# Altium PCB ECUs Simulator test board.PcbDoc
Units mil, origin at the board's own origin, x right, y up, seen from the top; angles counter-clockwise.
Board outline 2945 x 3010 mil, 2 copper layers (Top Layer, Bottom Layer), stack 12.8 mil thick; 62 components, 38 nets, 262 pads, 144 vias.
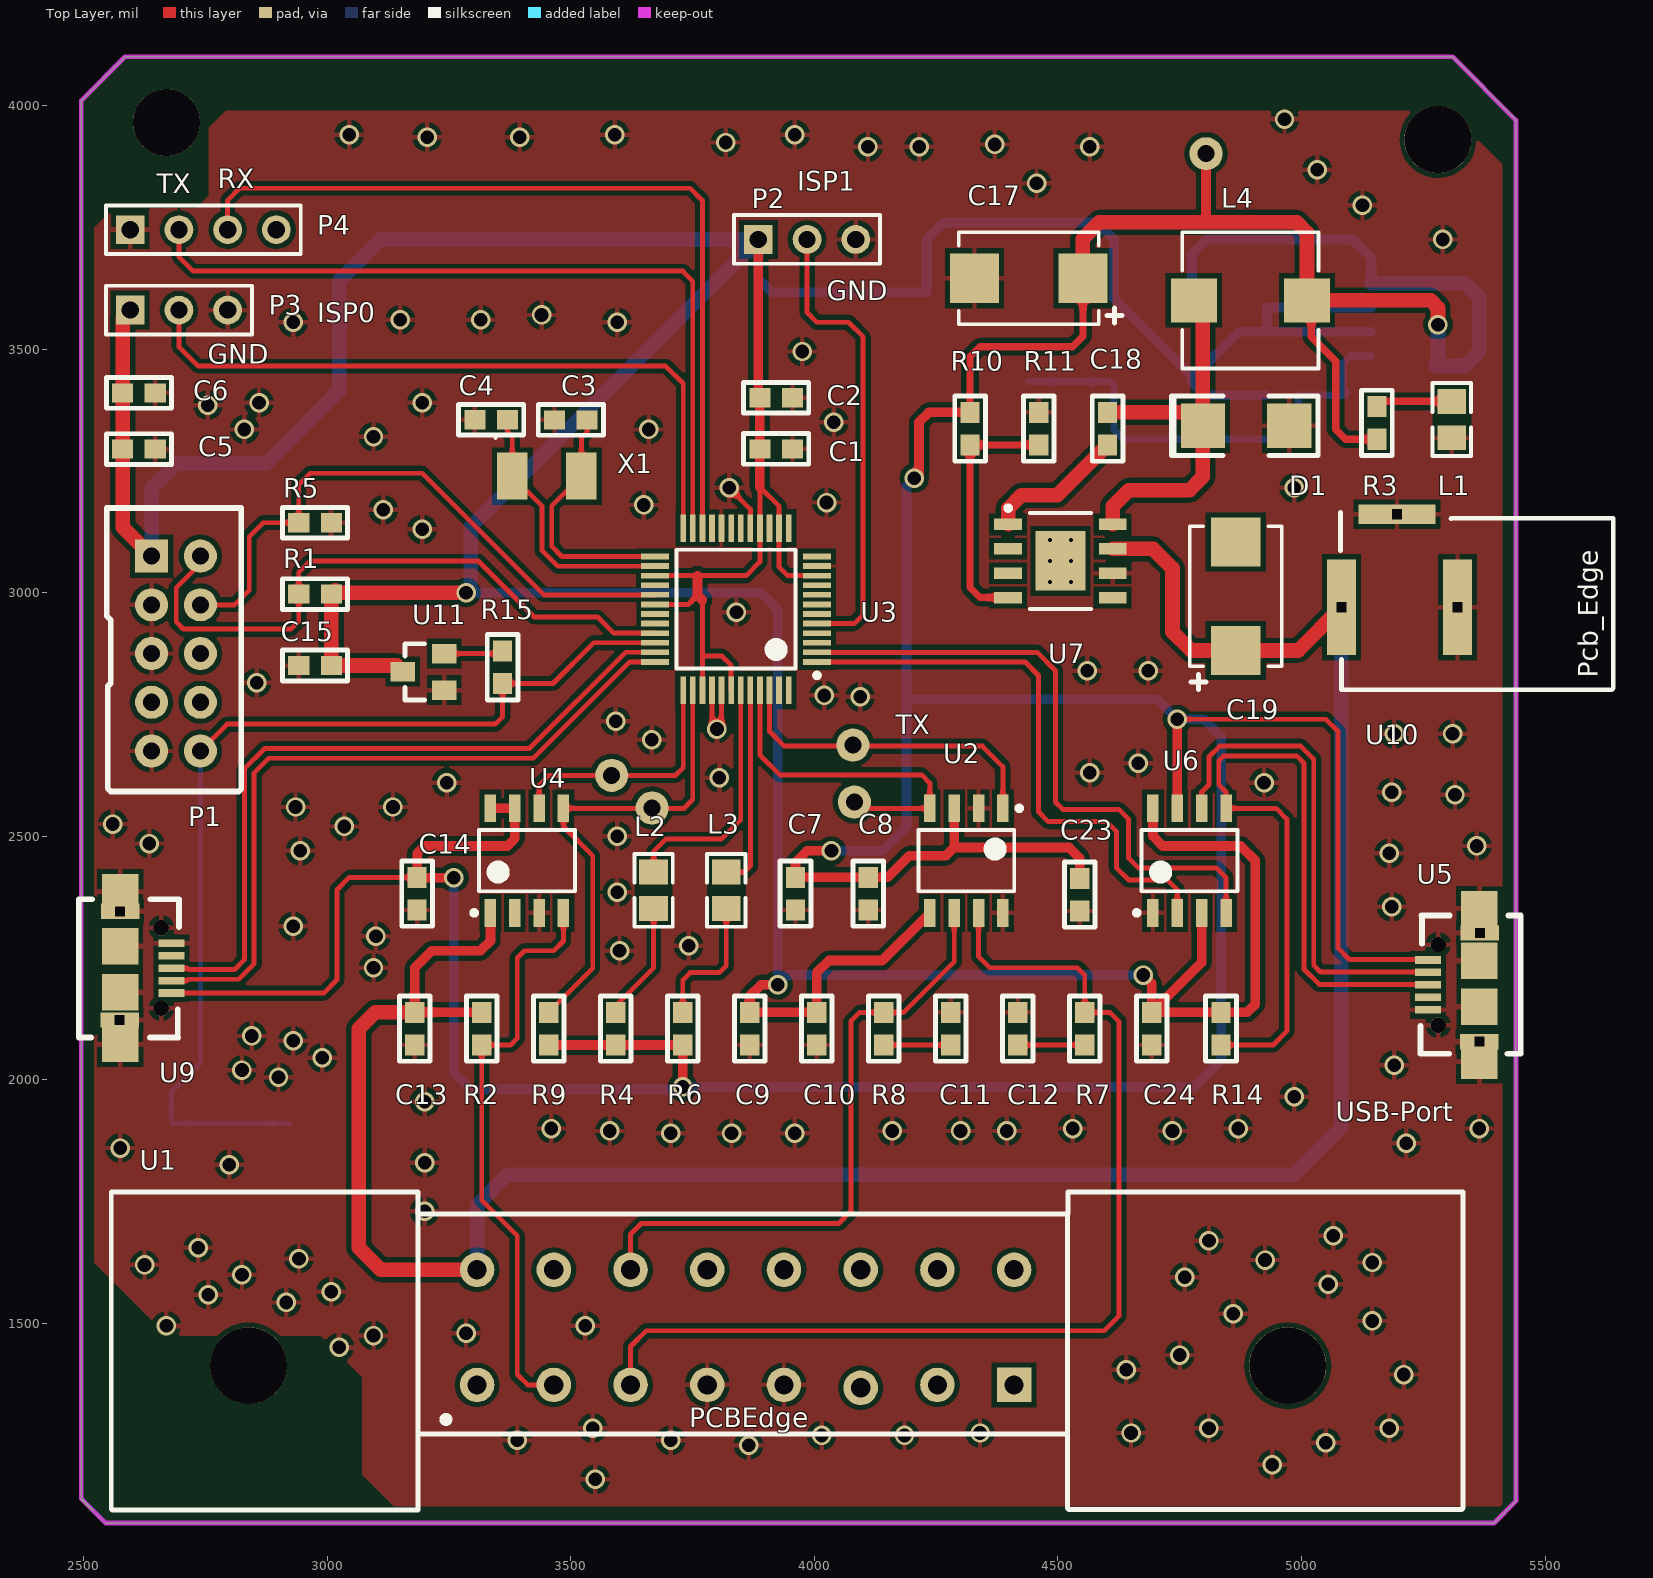
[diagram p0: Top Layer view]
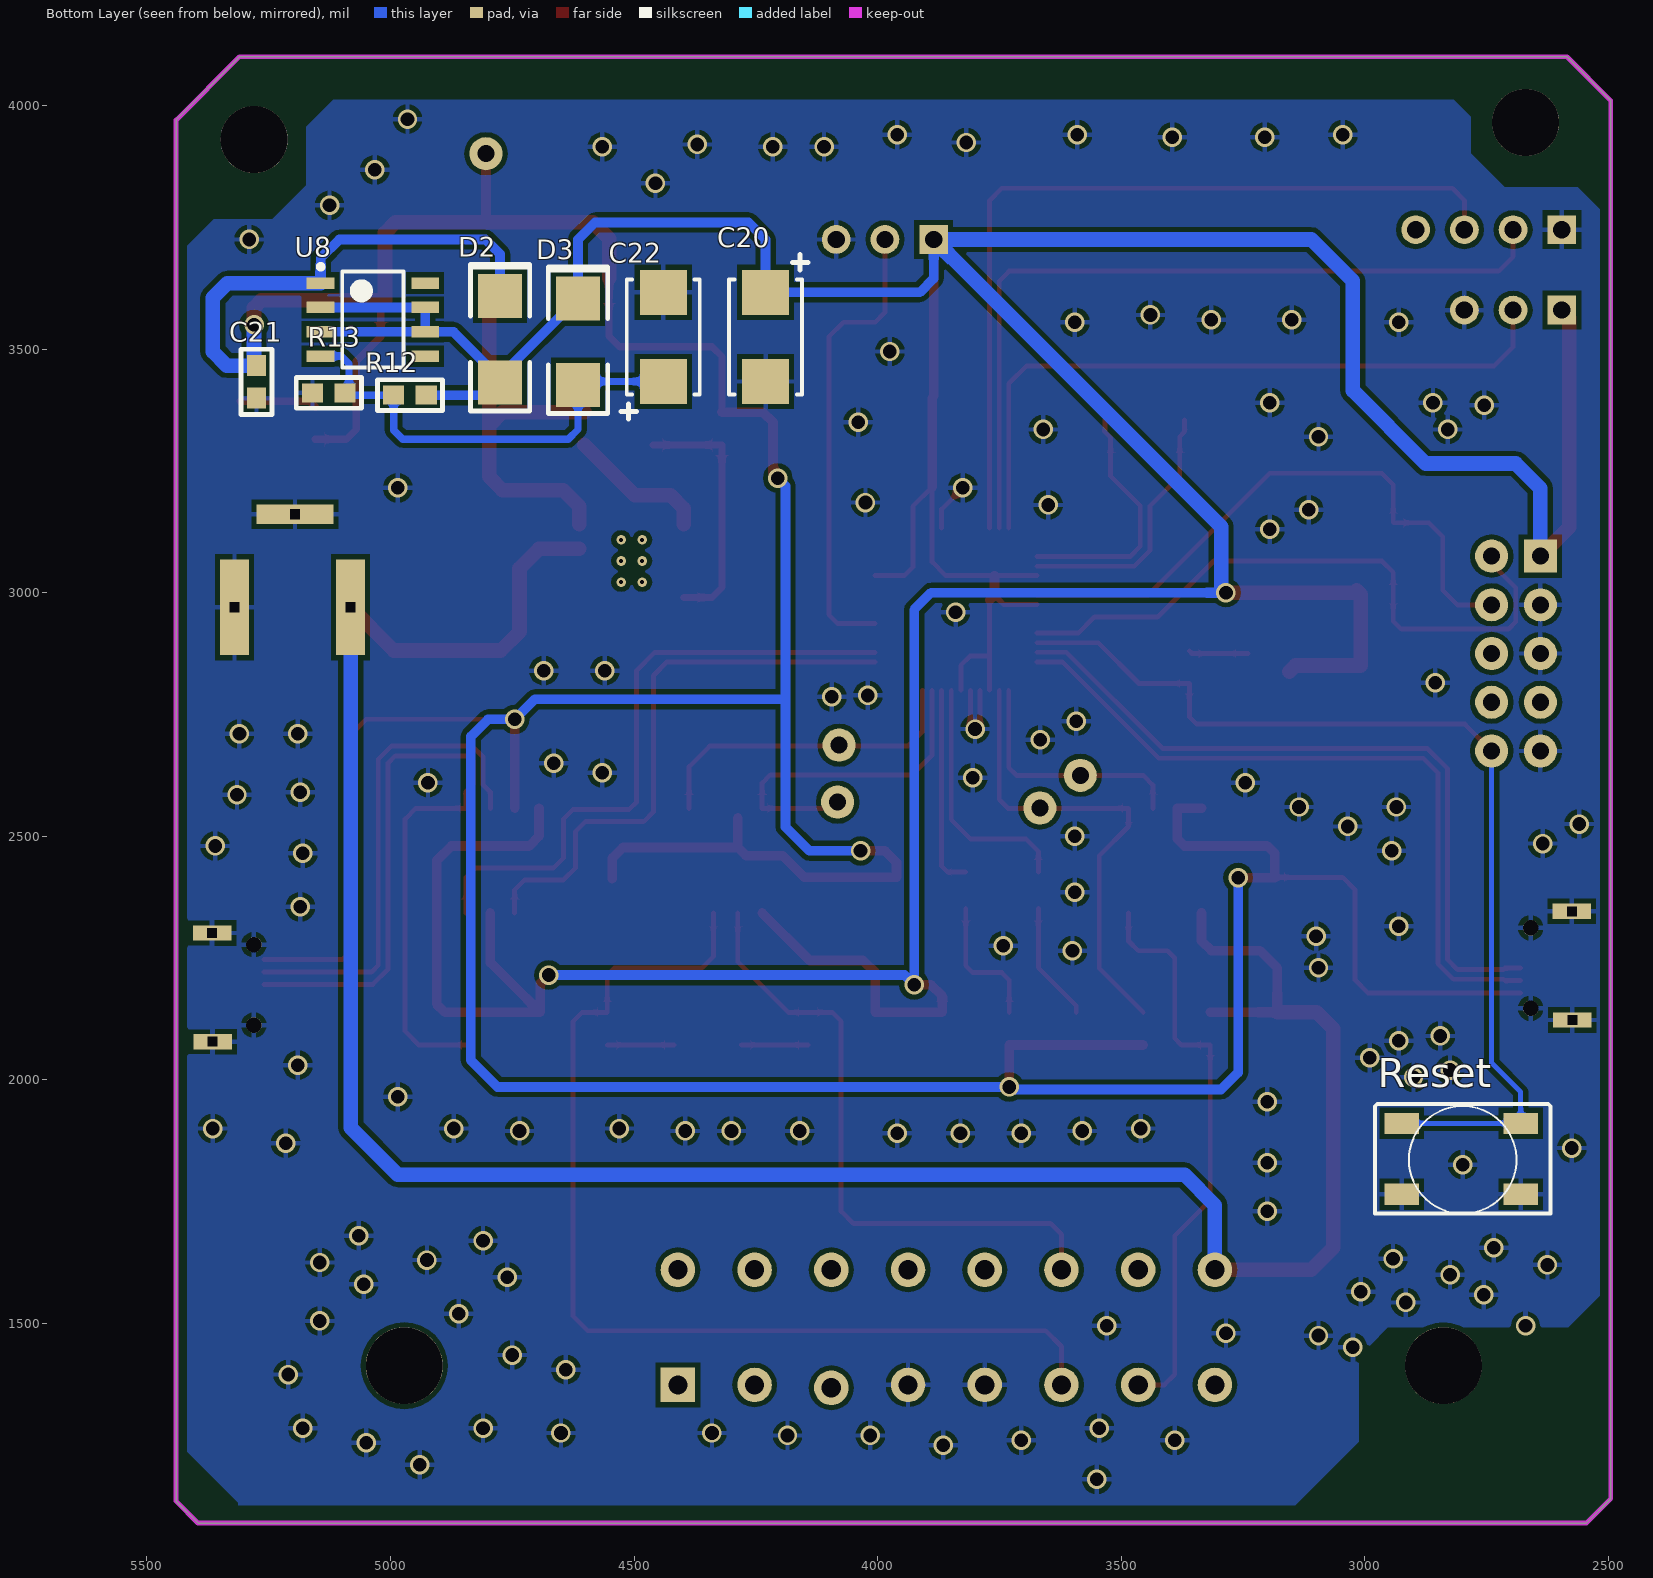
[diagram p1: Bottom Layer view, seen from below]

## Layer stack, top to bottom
Top Solder: solder mask 0.4, Solder Resist, Dk 3.5
Top Layer: signal copper 1.4
Dielectric 1: core 10, FR-4, Dk 4.2
Bottom Layer: signal copper 1.4
Bottom Solder: solder mask 0.4, Solder Resist, Dk 3.5

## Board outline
2495,1140 2495,4010 2585,4100 5310,4100 5440,3970 5440,1135 5395,1090 2545,1090

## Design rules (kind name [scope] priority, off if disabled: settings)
Clearance [All] p1: gap=10
DiffPairsRouting [All] p1: maxlimit=10 minlimit=10 mostfreqgap=10 toplayer_minwidth=10 toplayer_maxwidth=15 toplayer_prefwidth=15 bottomlayer_minwidth=10 bottomlayer_maxwidth=15 bottomlayer_prefwidth=15 maxuncoupledlength=500
PolygonConnect [All] p1: connectstyle=Relief reliefconductorwidth=10 reliefentries=4 polygonreliefangle="90 Angle" airgapwidth=10
RoutingVias [All] p1: holewidth=20 width=32 viastyle="Through Hole" minholewidth=15 minwidth=25 maxholewidth=28 maxwidth=40
SolderMaskExpansion [All] p1: expansion=4
Width [All] p1: maxlimit=30 minlimit=10 preferedwidth=10
29 further rules are at their usual default settings.

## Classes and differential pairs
component class USB: U9
component class Power: C17 C18 C19 C20 C21 C22 D1 D2 D3 L4 R10 R11 R12 R13 U7 U8 U10
component class PL2303A: C23 C24 R14 U5 U6
component class Core: C1 C2 C3 C4 C5 C6 C7 C8 C9 C10 C11 C12 C13 C14 C15 L1 L2 L3 P1 P2 P3 P4 R1 R2 R3 R4 R5 R6 R7 R8 R9 R15 Reset U1 U2 U3 U4 U11 X1

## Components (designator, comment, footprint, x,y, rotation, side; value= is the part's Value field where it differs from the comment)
C1 "10uF" 0603 3921.54,3295.39 r180 top
C2 "0.1uF" 0603 3921.54,3400.39 r180 top
C3 "22pF" 0603 3500,3355 r180 top
C4 "22pF" 0603 3336.54,3355.39 r180 top
C5 "4.7uF" 0603 2613.57,3295 r180 top
C6 "0.1uF" 0603 2613.57,3410.39 r180 top
C7 "0.1uF" 0603 3960.91,2382.1 r270 top
C8 "10uF" 0603 4110,2382.1 r270 top
C9 "10uF" 0603 3866.88,2105 r270 top
C10 "0.1uF" 0603 4004.41,2105 r270 top
C11 "560pF" 0603 4279.47,2105 r270 top
C12 "560pF" 0603 4417.01,2105 r270 top
C13 "0.1uF" 0603 3179.21,2105 r270 top
C14 "0.1uF" 0603 3185,2382.1 r90 top
C15 "0.1uF" 0603 2975,2850 r0 top
C17 "220uF" CAPM-7.0*4.5 4440,3645.32 r180 top
C18 "0.01uF" 0603 4602.18,3336.61 r90 top
C19 "10uF/16V" CAPM-7.0*4.5 4865,2992.46 r90 top
C20 "10uF/16V" CAPM-5.5*3.3 4230,3525 r270 bottom
C21 "0.1uF" 0603 5274.61,3432.62 r90 bottom
C22 "10uF/16V" CAPM-5.5*3.3 4440,3525 r90 bottom
C23 "10uF" 0603 4545,2380 r90 top
C24 "0.1uF" 0603 4692.86,2105 r90 top
D1 "B340A" DO214-AC 4886.16,3342.52 r180 top
D2 "1N4007" DO214-AC 4775,3520.2 r90 bottom
D3 "1N4007" DO214-AC 4615,3515 r90 bottom
L1 "LED" 0805 5308.41,3355.3 r270 top
L2 "LED" 0805 3670,2388.98 r90 top
L3 "LED" 0805 3819.09,2388.98 r90 top
L4 "4.7uH" 7*7*4-15uH 4895,3600.05 r0 top
P1 "Debug" JATG_10pin 2639.54,3075 r0 top
P2 "" HDR1X3 3885,3725 r0 top
P3 "" HDR1X3 2595.57,3580 r0 top
P4 "downloader" HDR1X4 2595.57,3745 r0 top
R1 "10K" 0603 2975,2997.3 r180 top
R2 "510R" 0603 3317.53,2105 r90 top
R3 "330R" 0603 5155,3348.43 r90 top
R4 "330R" 0603 3592.6,2105 r90 top
R5 "10K" 0603 2975,3143.8 r180 top
R6 "330R" 0603 3730.13,2105 r90 top
R7 "100R" 0603 4555.33,2105 r90 top
R8 "100R" 0603 4142.73,2105 r90 top
R9 "3.3K" 0603 3454.28,2105 r270 top
R10 "10K" 0603 4320,3336.61 r90 top
R11 "3.24K" 0603 4460.3,3336.61 r270 top
R12 "470R" 0603 4960,3405 r180 bottom
R13 "820R" 0603 5126.54,3409.61 r180 bottom
R14 "1.5K" 0603 4835,2105 r90 top
R15 "100K" 0603 3360.39,2846.93 r90 top
Reset "Button" BUtton-T4 2924.09,1910.67 r180 bottom (schematic designator S1)
U1 "OBD-Connector" OBD-Female 3307.64,1373.78 r0 top
U2 "TJF1051T / 3" TJF1051 4305,2448 r270 top
U3 "LPC1549" LPC1549JBD48 3840,2970 r180 top
U4 "MC33660EFR2" SOP-8 3410,2450 r90 top
U5 "MicroUSB" Micro-USB 5365,2037.4 r180 top
U6 "PL2303SA" SOP-8 4770,2450 r90 top
U7 "TPS5430" TPS5430 4505,3065 r0 top
U8 "LM317L" LM317L 5035,3560.44 r180 bottom
U9 "MicroUSB" Micro-USB 2575,2386.69 r0 top
U10 "DC-12V-Conector" DC-12V-Con 5081.81,2800.71 r0 top
U11 "IMP809TEUR-T" SOT23-3 3155,2837.99 r90 top
X1 "12MHZ" 12Mhz-DFN 3450,3240 r180 top

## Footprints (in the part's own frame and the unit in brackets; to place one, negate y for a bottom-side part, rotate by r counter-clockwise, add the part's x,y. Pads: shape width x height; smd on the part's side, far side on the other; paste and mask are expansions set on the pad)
7*7*4-15uH [mm] "Precision Wire Wound Inductor, 2-Leads, Body 7.00x7.00mm, IPC Medium Density"
  rect 2.4x2.3 smd: 1(-2.95,0) 2(2.95,0)
  silkscreen extent -3.55,-3.55 3.55,3.55
12Mhz-DFN [mm]
  rect 1.6x2.45 smd: 1(1.78,0.025) 2(-1.82,0.025)
  silkscreen extent 2.6,-2.02 2.7,-1.92, body extent -2.65,-1.57 2.65,1.63, height 0.45
0603 [mm]
  rect 1.1x1 smd: 1(-0.85,0.01) 2(0.85,0.01)
  silkscreen extent -1.7,-0.79 1.7,0.81
0805 [mm]
  rect 1.3x1.5 smd: 1(-0.95,0) 2(0.95,0)
  silkscreen extent -1.9,-1 1.9,1
BUtton-T4 [mm] "4*4*1.5"
  rect 1.8x1.1 smd: 1(0,0) 1(6.2,0) 2(0,-3.7) 2(6.2,-3.7)
  silkscreen extent -1.4,-4.71 7.75,1.02
CAPM-5.5*3.3 [mm]
  rect 2.35x2.45 smd: 1(-2.325,0) 2(2.325,0)
  silkscreen extent -4.29,-1.9 3,2.2
CAPM-7.0*4.5 [mm] "Molded Capacitor, 2-Leads, Body 7.00x4.50mm, IPC Medium Density"
  rect 2.55x2.6 smd: 1(-2.825,0) 2(2.825,0)
  silkscreen extent -4.87,-2.4 3.65,2.4
DC-12V-Con [mm]
  rect 1.5x5 hole 0.5 square: 1(0,4.3) 2(6.05,4.3)
  rect 4x1 hole 0.5 square: 3(2.9,9.15)
  silkscreen extent -0.05,0 14.17,9.25
DO214-AC [mm]
  rect 2.3x2.3 smd: 1(-2.25,0) 2(2.25,0)
  silkscreen extent -3.75,-1.55 3.9,1.55
HDR1X3 [mm] "Connector; Header; 3 Position"
  rect 1.5x1.5 hole 0.9: 1(0,0)
  round 1.5 hole 0.9: 2(2.54,0) 3(5.08,0)
  silkscreen extent -1.27,-1.27 6.35,1.27
HDR1X4 [mm] "Connector; Header; 4 Position"
  rect 1.5x1.5 hole 0.9: 1(0,0)
  round 1.5 hole 0.9: 2(2.54,0) 3(5.08,0) 4(7.62,0)
  silkscreen extent -1.27,-1.27 8.89,1.27
JATG_10pin [mil]
  rect 68x68 hole 35: 1(0,0)
  round 68 hole 35: 2(100,0) 3(0,-100) 4(100,-100) 5(0,-200) 6(100,-200) 7(0,-300) 8(100,-300) 9(0,-400) 10(100,-400)
  silkscreen extent -92,-483 184,99
LM317L [mm]
  rect 1.45x0.6 smd: 1(-2.75,1.905) 2(-2.75,0.635) 3(-2.75,-0.635) 4(-2.75,-1.905) 5(2.7,-1.905) 6(2.7,-0.635) 7(2.7,0.635) 8(2.7,1.905)
  silkscreen extent -2.88,-2.5 1.57,2.88
LPC1549JBD48 [mm]
  rect 1.45x0.3 smd: 1(-4.2,2.852) 2(-4.2,2.352) 3(-4.2,1.852) 4(-4.2,1.352) 5(-4.2,0.852) 6(-4.2,0.352) 7(-4.2,-0.148) 8(-4.2,-0.648) 9(-4.2,-1.148) 10(-4.2,-1.648) 11(-4.2,-2.148) 12(-4.2,-2.648) 25(4.25,-2.648) 26(4.25,-2.148) 27(4.25,-1.648) 28(4.25,-1.148) 29(4.25,-0.648) 30(4.25,-0.148) 31(4.25,0.352) 32(4.25,0.852) 33(4.25,1.352) 34(4.25,1.852) 35(4.25,2.352) 36(4.25,2.852)
  rect 0.3x1.45 smd: 13(-2.725,-4.123) 14(-2.225,-4.123) 15(-1.725,-4.123) 16(-1.225,-4.123) 17(-0.725,-4.123) 18(-0.225,-4.123) 19(0.275,-4.123) 20(0.775,-4.123) 21(1.275,-4.123) 22(1.775,-4.123) 23(2.275,-4.123) 24(2.775,-4.123) 37(2.775,4.327) 38(2.275,4.327) 39(1.775,4.327) 40(1.275,4.327) 41(0.775,4.327) 42(0.275,4.327) 43(-0.225,4.327) 44(-0.725,4.327) 45(-1.225,4.327) 46(-1.725,4.327) 47(-2.225,4.327) 48(-2.725,4.327)
  silkscreen extent -4.32,-3 3.13,3.68
Micro-USB [mm]
  rect 2x0.8 hole 0.5 square: 1(-0.025,-6.706) 1(0,-1.041)
  rect 1.9x1.8 smd: 1(0,0) 1(0,-8)
  rect 1.9x1.9 smd: 1(0,-2.85) 1(0,-5.25)
  round 0.8 hole 0.8: 1(2.15,-1.9) 1(2.15,-6.1)
  rect 1.35x0.4 smd: 1(2.675,-2.7) 2(2.675,-3.35) 3(2.675,-4) 4(2.675,-4.65) 5(2.675,-5.3)
  silkscreen extent -2.16,-7.62 3.07,-0.41
OBD-Female [mm]
  rect 1.8x1.8 hole 1: 1(28,0)
  round 1.8 hole 1: 2(24,0) 3(20,-0.152) 4(16,0) 5(12,0) 6(8,0) 7(4,0) 8(0,0) 9(28,6) 10(24,6) 11(20,6) 12(16,6) 13(12,6) 14(8,6) 15(4,6) 16(0,6)
  round 4 hole 4: ""(-11.913,1) ""(42.266,1)
  silkscreen extent -19.08,-6.53 51.41,10.06
SOP-8 [mm]
  rect 1.45x0.6 smd: 1(-2.725,1.905) 2(-2.725,0.635) 3(-2.725,-0.635) 4(-2.725,-1.905) 5(2.725,-1.905) 6(2.725,-0.635) 7(2.725,0.635) 8(2.725,1.905)
  silkscreen extent -2.85,-2.5 1.6,2.88
SOT23-3 [mil]
  rect 40x50 smd: 1(-37.99,-85) 2(37.01,-85) 3(0.01,0)
  silkscreen extent -58,-45 57,-5
TJF1051 [mm]
  rect 1.45x0.6 smd: 1(-2.776,2.083) 2(-2.776,0.813) 3(-2.776,-0.457) 4(-2.776,-1.727) 5(2.674,-1.727) 6(2.674,-0.457) 7(2.674,0.813) 8(2.674,2.083)
  silkscreen extent -2.9,-2.32 1.55,3.06
TPS5430 [mm]
  rect 1.45x0.6 smd: 1(-2.725,1.905) 2(-2.725,0.635) 3(-2.725,-0.635) 4(-2.725,-1.905) 5(2.725,-1.905) 6(2.725,-0.635) 7(2.725,0.635) 8(2.725,1.905)
  rect 2.6x3.1 smd: 9(0,0)
  silkscreen extent -2.85,-2.5 1.6,2.88

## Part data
C1 C2 C3 C4 C5 C6 C7 C8 C9 C10 C11 C12 C13 C14 C15 C18 C21 C23 C24: library part Cap1, "ceramic"
C17 C19 C20 C22: library part Cap3, "aluminum"
D1: library part B340A-13-F
L4: library part Inductor
P1: library part JTAG_10Pin
P2 P3: library part "Header 3", "Header, 3-Pin"
P4: library part "Header 4", "Header, 4-Pin"
R1 R2 R3 R4 R5 R6 R7 R8 R9 R10 R11 R12 R13 R14 R15: library part Res
U1: library part OBD-MaleHead
U3: library part LPC1549JBD48
U5 U9: library part MicroUSB_B
U10: library part DC12V-Connector
X1: library part OSC

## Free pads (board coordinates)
  round 137.8 hole 137.8: 0(2670,3965) 1(5280,3930)
  round 68 hole 35: 2(3584,2625) 3(3667,2558) 4(4079,2687) 5(4082,2570) 6(4804,3901)

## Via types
v1: diameter 40, hole 28, Top Layer to Bottom Layer, 138 vias
v2: diameter 19.68, hole 7.87, Top Layer to Bottom Layer, 6 vias

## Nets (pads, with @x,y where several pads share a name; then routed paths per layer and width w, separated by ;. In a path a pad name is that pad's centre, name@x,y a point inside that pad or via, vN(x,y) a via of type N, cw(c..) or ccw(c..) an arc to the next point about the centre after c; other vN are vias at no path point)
3.3V: C1.2 C2.2 C5.2 C6.2 C9.1 C10.1 C15.2 C20.1 C24.2 D2.1 D3.2 P1.1 P2.1 P3.1 R1.1 R12.2 R14.2 U2.5 U3.10 U3.14 U3.16 U3.27 U3.30 U3.39 U3.42 U6.3 U6.8 U8.2 U8.3 U8.6 U8.7 U11.3 | length 11474.4
  Top Layer w10: U3.30 3740.84,2975.84 3760,2995 ; U3.27 3760,3034.9 3859.9,3034.9 3888.21,3063.21 U3.16 3888.21,3216.79 ; 3770,2985 3770,2870 3770.1,2870 ; U3.39 3770.1,2870 ; U3.42 3829.16,2850.84 3810,2870 3770.1,2870 ; 3888.07,3216.93 3888.21,3216.79 ; U3.10 3945,3034.9 3945,3035 3927.58,3052.42 U3.14 3927.58,3177.42 3888.21,3216.79
  Top Layer w20: 3760,3034.9 3760,2995 3770,2985 ; P2.1 3885,3403.07 C2.2 C1.2 3888.07,3216.93 ; v1(3925,2195) 3890,2195 3867.27,2172.27 C9.1 C10.1 4004.8,2219.8 4030,2245 4139.28,2245 U2.5 ; v1(4675,2215) 4692.47,2197.53 C24.2 ; U6.8 4695,2500 4715,2480 4875,2480 4905,2450 4905,2155 4888.46,2138.46 R14.2 C24.2 ; U6.3 4795,2241 C24.2
  Top Layer w30: P3.1 2580.1,3564.53 C6.2 C5.2 2580,3294.5 2580,3134.54 P1.1 ; U11.3 3142.61,2850.39 C15.2 R1.1 3016.56,3005 3021.56,3000 v1(3285,3000)
  Bottom Layer w20: v1(3285,3000) 3890,3000 3925,2965 v1(3925,2195) 3945,2215 v1(4675,2215) ; P2.1 3885,3645 3913.46,3616.54 C20.1 4230,3725 4265,3760 4580,3760 4615,3725 D3.2 4775,3443.58 D2.1@4775,3440 ; R12.2 4801.23,3405.39 D2.1 D2.1@4775,3440 ; U8.3 U8.6 ; U8.2 U8.7 U8.6 ; D2.1@4775,3440 4870.44,3535.44 U8.6
  Bottom Layer w30: P1.1 2639.54,3214.54 2690,3265 2875,3265 3025,3415 3025,3640 3110,3725 P2.1@3860,3725 ; v1(3285,3000) 3295,3010 3295,3135 P2.1
5V: C7.1 C8.1 C14.2 C17.1 C21.2 C23.2 D2.2 L4.2 pad.6 R3.1 R4.1 R6.1 R9.2 R10.2 U2.3 U4.7 U4.8 U5.5 U6.7 U8.1 U9.5 | length 11090.1
  Top Layer w10: U9.5 2993.03,2178.03 3020,2205 3020,2390 3045.57,2415.57 C14.2 ; v1(4745,2740) 5050,2740 5075,2715 5075,2270 5098.03,2246.97 U5.5@5259.69,2246.97
  Top Layer w15: R10.2 4319.61,3484.61 4340,3505 4530,3505 4551.22,3526.22 C17.1 ; L4.2 5020,3591.19 5020,3525 5070,3475 5070,3335 5090.04,3314.96 R3.1
  Top Layer w20: v1(3260,2415) 3185.17,2415 C14.2 3184.61,2464.61 3200,2480 3370,2480 3385,2495 U4.7 U4.8 ; R9.2 R4.1 R6.1 v1(3729.74,1985.26) ; v1(4035,2470) 3985,2470 3961.3,2446.3 C7.1 C8.1 4150.57,2415.57 4195,2460 4270,2460 4287,2477 ; v1(4205,3235) 4215,3245 4215,3350 4235.08,3370.08 R10.2 ; U2.3@4287,2537.28 4287,2477 ; C23.2 4544.61,2455.39 4523,2477 4287,2477 ; U6.7 v1(4745,2740) ; 4802,3760 4804,3762 pad.6
  Top Layer w30: C17.1 4551.22,3726.22 4585,3760 4802,3760 4990,3760 5011.14,3738.86 L4.2 5264.95,3600.05 5280,3585 v1(5280,3550)
  Bottom Layer w20: v1(3260,2415) 3260,2015 3295,1980 3724.47,1980 v1(3729.74,1985.26) 4780.26,1985.26 4835,2040 4835,2705 4800,2740 v1(4745,2740) 4704,2781 4189,2781 ; v1(4035,2470) 4140,2470 4189,2519 4189,2781 ; v1(4205,3235) 4189,3219 4189,2781 ; D2.2 4775,3695 4805,3725 5105,3725 5143.28,3686.72 U8.1
  Bottom Layer w30: U8.1 5334.56,3635.44 5365,3605 5365,3495 5336.09,3466.09 C21.2 5280,3471.09 v1(5280,3550)
12V: C13.1 C19.1 R2.2 U1.16 U4.1 U7.7 U10.1 | length 5014.3
  Top Layer w20: R2.2 C13.1 3179.61,2229.61 3215,2265 3315,2265 3335,2285 U4.1
  Top Layer w30: C13.1 3098.46,2138.46 3065,2105 3065,1655 3110,1610 U1.16 ; U7.7 4695,3090 4735,3050 4735,2920 4773.76,2881.24 C19.1 4993.05,2881.24 U10.1
  Bottom Layer w30: U1.16 3307.64,1742.64 3370,1805 4985,1805 5081.81,1901.81 U10.1
ADJ: C22.1 D3.1 R12.1 R13.2 U8.4 | length 965.2
  Bottom Layer w15: C22.1 4607.95,3433.46 D3.1 4615,3335 4635,3315 4975,3315 4993.46,3333.46 R12.1 5088.46,3405.39 R13.2 5085,3418.07 5085,3470 5100.44,3485.44 U8.4
BOOT: C18.1 U7.1 | length 290.8
  Top Layer w30: U7.1 4397.72,3172.72 4425,3200 4498.63,3200 C18.1
CAN_H: R7.2 U1.6 U2.7 | length 2189.7
  Top Layer w10: U1.6 3622.6,1452.6 3655,1485 4595,1485 4625,1515 4625,2120 4606.54,2138.46 R7.2 4554.93,2214.93 4539.87,2230 4360,2230 4337,2253 U2.7
CAN_L: R8.2 U1.14 U2.6 | length 1297.9
  Top Layer w10: U1.14 3622.6,1682.6 3645,1705 4050,1705 4075,1730 4075,2120 4093.46,2138.46 R8.2 4183.46,2138.46 4287,2242 U2.6
D+: U3.35 U9.3 | length 1492.8
  Top Layer w10: U9.3 2711.89,2229.21 2714.69,2226.42 2810,2226.42 2830,2246.42 2830,2638.28 2871.72,2680 3415,2680 3612.73,2877.73 U3.35@3672.66,2877.73
D-: U3.36 U9.4 | length 1492.8
  Top Layer w10: U9.4 2711.89,2203.62 2714.69,2206.42 2818.28,2206.42 2850,2238.13 2850,2630 2880,2660 3423.28,2660 3621.02,2857.73 U3.36
GND: C1.1 C2.1 C3.2 C4.2 C5.1 C6.1 C7.2 C8.2 C9.2 C10.2 C11.1 C12.1 C13.2 C14.1 C15.1 C17.2 C20.2 C21.1 C22.2 C23.1 C24.1 D1.1 L1.2 P1.3 P1.5 P1.9 P2.3 P3.3 P4.1 R5.1 R11.1 R13.1 Reset.2 U1.4 U1.5 U2.2 U2.8 U3.11 U3.17 U3.20 U3.40 U3.41 U4.3 U5.1 U6.1 U7.6 U9.1 U10.2 U10.3 U11.1 | length 268.2
  Top Layer w10: U3.40 3789.79,2730.21 v1(3800,2720) 3809.47,2729.47 U3.41 ; v1(3825,3215) 3868.53,3171.47 U3.17
  other v1: 3550,1180 4940,1210 3865,1250 5050,1255 3390,1260 3705,1260 4015,1270 4185,1270 4340,1275 4650,1275 3545,1285 4810,1285 5180,1285 5210,1395 4640,1405 4750,1435 3025,1451 3095,1475 3285,1480 2670,1495 3530,1495 5145,1505 4860,1520 2916,1543 2756,1559 3008,1565 5055,1580 4760,1595 2825,1600 2625,1620 5145,1625 4925,1630 2942,1633 2735,1655 4810,1670 5065,1680 3200,1730 2799,1826 3200,1830 2575,1860 5215,1870 3705,1890 3830,1890 3960,1890 3580,1895 4160,1895 4300,1895 4395,1895 4735,1895 3460,1900 4530,1900 4870,1900 5365,1900 3200,1955 4985,1965 2900,2005 2825,2020 5190,2030 2990,2045 2930,2080 2845,2090 3095,2230 3600,2265 3742,2275 3100,2295 2930,2315 5185,2355 3595,2385 5180,2465 2945,2470 5360,2480 2635,2485 3595,2500 3035,2520 2560,2525 2935,2560 3135,2560 5315,2585 5185,2590 3245,2610 4923,2610 3805,2620 4565,2630 4665,2650 3666,2698 5190,2710 5310,2710 3592,2736 4094,2786 4020,2789 2855,2815 4560,2840 4685,2840 3840,2960 3195,3130 3115,3170 3650,3180 4025,3185 4985,3215 3095,3320 2830,3335 3660,3335 4040,3350 2755,3385 2860,3390 3195,3390 3975,3495 2930,3555 3595,3555 3150,3560 3315,3560 3440,3570 5290,3725 5125,3795 4456,3840 5032,3868 4110,3915 4215,3915 4565,3915 4370,3920 3818,3924 3205,3935 3395,3935 3045,3940 3590,3940 3960,3940 4965,3972
ISP0: P2.2 U3.5 | length 958
  Top Layer w10: P2.2 3985,3575 4005,3555 4070,3555 4100,3525 4100,2955 4081.47,2936.47 U3.5
ISP1: P3.2 U3.24 | length 1438.8
  Top Layer w10: P3.2 2695.57,3504.43 2735,3465 3695,3465 3730.73,3429.27 U3.24
K-LINE: R2.1 U1.7 U4.4 | length 1201.3
  Top Layer w10: U1.7 3411.22,1373.78 3390,1395 3390,1680 3317.14,1752.86 R2.1 3376.54,2071.54 3390,2085 3390,2250 3405,2265 3465,2265 3485,2285 U4.4
NetC3_1: C3.1 U3.25 X1.2 | length 510.2
  Top Layer w10: C3.1 3533.46,3329.92 3521.65,3318.11 X1.2 3460.79,3178.13 3460.79,3095 3481.52,3074.27 U3.25
NetC4_1: C4.1 U3.26 X1.1 | length 542.9
  Top Layer w10: C4.1 3370,3330.32 3379.92,3320.39 X1.1 3440.79,3178.13 3440.79,3086.72 3473.24,3054.27 U3.26@3672.66,3054.27
NetC11_2: C11.2 R8.1 | length 137.5
  Top Layer w10: R8.1 C11.2
NetC12_2: C12.2 R7.1 | length 137.5
  Top Layer w10: C12.2 R7.1
NetC18_2: C18.2 D1.2 L4.1 U7.8 | length 825
  Top Layer w30: C18.2 4770.02,3370.08 D1.2 ; U7.8 4612.28,3177.28 4645,3210 4770,3210 4797.58,3237.58 D1.2 ; L4.1 4797.58,3581.33 D1.2
NetL1_1: L1.1 R3.2 | length 158.3
  Top Layer w15: R3.2 5165.42,3392.7 L1.1
NetL2_1: L2.1 R4.2 | length 245.3
  Top Layer w10: R4.2 3592.2,2152.2 3670,2230 L2.1
NetL3_1: L3.1 R6.2 | length 285.3
  Top Layer w10: R6.2 3729.74,2204.74 3745,2220 3805,2220 3819.09,2234.09 L3.1
NetR9_1: pad.3 R9.1 U3.38 U4.5 | length 978.3
  Top Layer w10: R9.1 3545,2228.79 3545,2460 3485,2520 U4.5 3732.28,2557.28 3750.42,2575.42 U3.38
NetR14_1: R14.1 U5.3 U6.5 | length 1696.5
  Top Layer w10: R14.1 4941.54,2071.54 4970,2100 4970,2535 4947.72,2557.28 U6.5 4845,2590.83 4830,2605.83 4830,2655 4840,2665 4990,2665 5005,2650 5005,2226.72 5035.93,2195.79 U5.3@5259.69,2195.79
NetR15_2: R15.2 U11.2 | length 122.2
  Top Layer w10: U11.2 3354.61,2875 R15.2
NetU2_1: pad.4 U2.1 U3.46 | length 679.2
  Top Layer w10: U3.46 3907.9,2715.1 3938,2685 4345,2685 4387,2643 U2.1
NetU2_4: pad.5 U2.4 U3.45 | length 717.6
  Top Layer w10: U3.45 3888.21,2666.79 3929,2626 4220,2626 4237,2609 U2.4 4094.72,2557.28 pad.5
NetU3_37: pad.2 U3.37 U4.6 | length 517.2
  Top Layer w10: U4.6 3435,2605 3455,2625 pad.2 3715,2625 3730.73,2640.73 U3.37
NetU5_4: U5.4 U6.6 | length 1010.9
  Top Layer w10: U6.6 4795,2590.83 4810,2605.83 4810,2663.28 4831.72,2685 4993.28,2685 4998.28,2685 5025,2658.28 5025,2235 5038.62,2221.38 U5.4@5259.69,2221.38
PIN_43: L2.2 U3.43 | length 514.1
  Top Layer w10: L2.2 3670,2469 3695,2494 3809,2494 3848.84,2533.84 U3.43
PIN_44: L3.2 U3.44 | length 415.6
  Top Layer w10: L3.2 3856.38,2426.38 3868.53,2438.53 U3.44
R\S\T\: P1.10 R15.1 Reset.1 U3.34 | length 2098.3
  Top Layer w10: P1.10 2794.54,2730 3345,2730 3360,2745 R15.1 3463.46,2813.46 3547.1,2897.1 U3.34
  Bottom Layer w10: P1.10 2739.54,2034.54 2680,1975 2680,1910.67 Reset.1@2924.09,1910.67
RX: P4.3 U3.22 | length 1728.2
  Top Layer w10: P4.3 2795.57,3805.57 2820,3830 3745,3830 3770.1,3804.9 U3.22
SWDCLK: P1.4 R5.2 U3.29 | length 1258.5
  Top Layer w10: P1.4 2810,2975 2840,3005 2840,3115 2868.41,3143.41 R5.2 2941.54,3221.54 2965,3245 3195,3245 3444.47,2995.53 U3.29
SWDIO: P1.2 R1.2 U3.33 | length 1322.4
  Top Layer w10: P1.2 2739.54,3059.54 2690,3010 2690,2940 2705,2925 2925,2925 2941.54,2941.54 R1.2 2941.54,3041.54 2965,3065 3310,3065 3425,2950 3555,2950 3588.21,2916.79 U3.33
TX: P4.2 U3.23 | length 1638.3
  Top Layer w10: P4.2 2695.57,3689.43 2725,3660 3730,3660 3750.42,3639.58 U3.23
UART_RX: U3.2 U6.4 | length 1308.5
  Top Layer w10: U3.2 4457.58,2877.42 4495,2840 4495,2570 4510,2555 4625,2555 4645,2535 4645,2455 4665,2435 4825,2435 4845,2415 U6.4
UART_TX: U3.1 U6.2 | length 1188.6
  Top Layer w10: U3.1 4432.27,2857.73 4460,2830 4460,2550 4480,2530 4600,2530 4620,2510 4620,2435 4644.74,2410.26 4724.74,2410.26 4745,2390 U6.2
VFB: R10.1 R11.2 U7.4 | length 520.4
  Top Layer w15: U7.4 4340,2990 4319.61,3010.39 R10.1 R11.2
pads on no net: C19.2 P1.6 P1.7 P1.8 P4.4 U1. U1.1 U1.2 U1.3 U1.8 U1.9 U1.10 U1.11 U1.12 U1.13 U1.15 U3.3 U3.4 U3.6 U3.7 U3.8 U3.9 U3.12 U3.13 U3.15 U3.18 U3.19 U3.21 U3.28 U3.31 U3.32 U3.47 U3.48 U4.2 U5.2 U7.2 U7.3 U7.5 U7.9 U8.5 U8.8 U9.2
copper on no net:
  other v2: 4483.35,3021.69 4526.65,3021.69 4483.35,3065 4526.65,3065 4483.35,3108.31 4526.65,3108.31

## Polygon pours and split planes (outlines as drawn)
GND on Top Layer "GND" (solid, remove dead copper, pour order 0): 3171.83,1124.48 5411.83,1124.48 5411.83,3879.48 5341.83,3949.48 5301.83,3989.48 5166.83,3989.48 2791.83,3989.48 2756.83,3954.48 2756.83,3839.48 2756.83,3814.48 2736.83,3794.48 2731.83,3789.48 2566.83,3789.48 2561.83,3789.48 2521.83,3749.48 2521.83,1639.48 2521.83,1624.48 2641.83,1504.48 2671.83,1474.48 2931.83,1474.48 2986.83,1474.48 3071.83,1389.48 3071.83,1199.48 3071.83,1189.48 3136.83,1124.48
GND on Bottom Layer "GND" (solid, remove dead copper, pour order 2): 3142.39,1126.73 3012.39,1256.73 3012.39,1351.73 3012.39,1431.73 2962.39,1481.73 2952.39,1491.73 2612.39,1491.73 2582.39,1491.73 2522.39,1551.73 2517.39,1556.73 2517.39,3776.73 2517.39,3786.73 2557.39,3826.73 2562.39,3831.73 2707.39,3831.73 2712.39,3831.73 2747.39,3866.73 2782.39,3901.73 2782.39,3971.73 2782.39,3976.73 2802.39,3996.73 2817.39,4011.73 4277.39,4011.73 5117.39,4011.73 5162.39,3966.73 5172.39,3956.73 5172.39,3836.73 5232.39,3776.73 5242.39,3766.73 5357.39,3766.73 5362.39,3766.73 5392.39,3736.73 5417.39,3711.73 5417.39,1311.73 5417.39,1236.73 5352.39,1171.73 5312.39,1131.73 5312.39,1126.73

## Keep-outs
Keep-Out Layer:
  lines w10: 2495,1140 2545,1090 5395,1090 5440,1135 5440,3970 5310,4100 2585,4100 2495,4010 2495,2010 2495,1140

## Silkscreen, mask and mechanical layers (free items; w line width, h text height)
Top Overlay:
  text "RX" at 2775,3830 h40
  text "ISP1" at 3965,3825 h40
  text "TX" at 2650,3820 h40
  text "GND" at 4025,3600 h40
  text "ISP0" at 2980,3555 h40
  text "GND" at 2755,3470 h40
  text "TX" at 4167,2709 h40
  text "USB-Port" at 5070,1915 h40

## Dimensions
2585,4100 to 2545,1090 on Top Overlay
2495,4010 to 5440,3970 on Top Overlay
